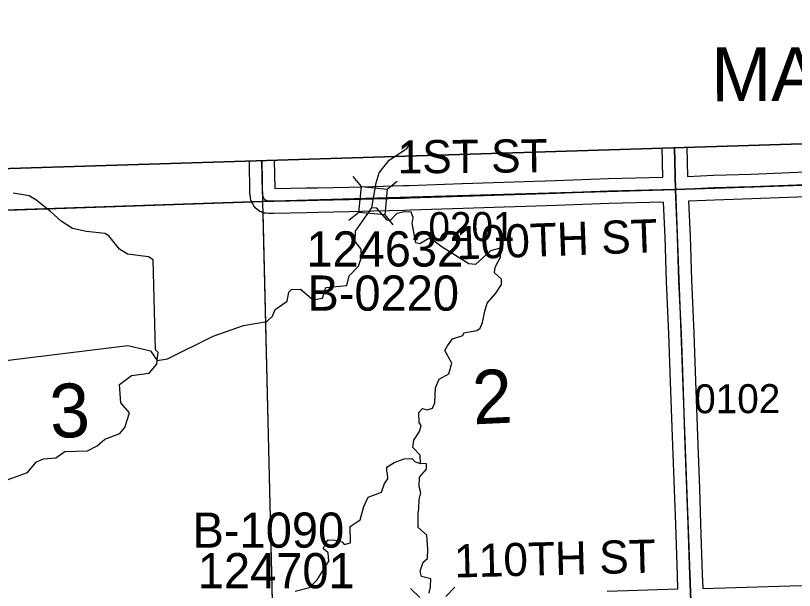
# Model space of a CAD drawing. Extents: x 128.7 to 185.5, y -21.4 to 12.6.
# Drawn here: x 143.177 to 145.06, y 3.674 to 5.063 of the extents above; entities that cross this region are included whole.
import ezdxf

# ---------------------------------------------------------------- set-up
doc = ezdxf.new("R2010")
doc.units = 0
for name, color, linetype in [('tdCoClipBndry', 7, 'Continuous'), ('tdCoCoAdjSecRdTxt', 7, 'Continuous'), ('tdCoCoBndry', 7, 'Continuous'), ('tdCoCoBndryPart', 7, 'Continuous'), ('tdCoCorpTxt', 7, 'Continuous'), ('tdCoHydroRiver', 7, 'Continuous'), ('tdCoSecRdNmbr', 7, 'Continuous'), ('tdCoSecRdTxt', 7, 'Continuous'), ('tdCoSecRteBand', 7, 'Continuous'), ('tdCoSecRteCL', 7, 'Continuous'), ('tdCoSectLine', 7, 'Continuous'), ('tdCoSectLinePart', 7, 'Continuous'), ('tdCoSectNmbr', 7, 'Continuous'), ('tdCoStrucSec', 7, 'Continuous'), ('tdCoStrucSecCoName', 7, 'Continuous'), ('tdCoStrucSecFHWANum', 7, 'Continuous'), ('tdCoSurfGravel', 7, 'Continuous'), ('tdCoTwpBndryShd', 7, 'Continuous')]:
    doc.layers.add(name, color=color, linetype=linetype)

msp = doc.modelspace()

# ---------------------------------------------------------------- linework, layer by layer
at = {"layer": 'tdCoClipBndry'}
msp.add_lwpolyline([(134.0612, -7.7025), (133.8962, -2.6807), (133.6887, 4.3446), (133.6938, 4.3792), (133.7053, 4.4028), (133.7226, 4.4226), (133.7445, 4.4372), (133.7868, 4.4475), (134.771, 4.4649), (135.7559, 4.4935), (136.7866, 4.5129), (139.7725, 4.5879), (146.7594, 4.806), (147.7608, 4.8492), (149.7557, 4.9088), (150.75, 4.946), (153.7332, 5.0633)], dxfattribs=at)
at = {"layer": 'tdCoCoBndry'}
for p, q in [((144.7722, 4.6433), (145.7757, 4.6779)), ((145.7757, 4.6779), (144.7722, 4.6433)), ((143.7746, 4.6139), (144.7722, 4.6433)), ((144.7722, 4.6433), (143.7746, 4.6139)), ((142.7681, 4.58), (143.7746, 4.6139)), ((143.7746, 4.6139), (142.7681, 4.58))]:
    msp.add_line(p, q, dxfattribs=at)
for points in [[(153.7332, 5.0633), (150.75, 4.946), (149.7557, 4.9088), (147.7608, 4.8492), (146.7594, 4.806), (139.7725, 4.5879), (136.7866, 4.5129)], [(136.7888, 4.4129), (137.7724, 4.4375), (137.7858, 4.438), (138.7769, 4.4617), (139.7753, 4.488), (140.7687, 4.5163), (141.7663, 4.5476), (142.7677, 4.58), (143.7742, 4.6139), (144.7719, 4.6433), (145.7753, 4.6779), (146.7631, 4.7061), (147.7638, 4.7493), (148.7588, 4.7767), (149.759, 4.8089), (150.7538, 4.8461), (150.7626, 4.8466), (151.7683, 4.8866), (152.7453, 4.9271), (153.73, 4.9634)], [(136.7891, 4.4129), (137.7728, 4.4375), (137.7862, 4.438), (138.7773, 4.4617), (139.7757, 4.488), (140.769, 4.5163), (141.7667, 4.5476), (142.7681, 4.58), (143.7746, 4.6139), (144.7722, 4.6433), (145.7757, 4.6779), (146.7635, 4.7061), (147.7642, 4.7493), (148.7592, 4.7767), (149.7594, 4.8089), (150.7542, 4.8461), (150.7629, 4.8466), (151.7687, 4.8866), (152.7457, 4.9271), (153.7304, 4.9634)], [(136.7891, 4.4129), (137.7728, 4.4375), (137.7862, 4.438), (138.7773, 4.4617), (139.7757, 4.488), (140.769, 4.5163), (141.7667, 4.5476), (142.7681, 4.58), (143.7746, 4.6139), (144.7722, 4.6433), (145.7757, 4.6779), (146.7635, 4.7061), (147.7642, 4.7493), (148.7592, 4.7767), (149.7594, 4.8089), (150.7542, 4.8461), (150.7629, 4.8466), (151.7687, 4.8866), (152.7457, 4.9271), (153.7304, 4.9634)]]:
    msp.add_lwpolyline(points, dxfattribs=at)
at = {"layer": 'tdCoCoBndryPart'}
msp.add_lwpolyline([(142.2951, 4.5647), (142.7677, 4.58), (143.7477, 4.613)], dxfattribs=at)
at = {"layer": 'tdCoHydroRiver'}
for points in [[(143.1297, 3.9317), (143.2061, 3.9595), (143.2274, 3.9854), (143.2445, 3.9923), (143.2744, 3.9949), (143.296, 4.0098), (143.3512, 4.0116), (143.3745, 4.0234), (143.3929, 4.0398), (143.4288, 4.0536), (143.4409, 4.0682), (143.4524, 4.1033), (143.4311, 4.1279), (143.4281, 4.172), (143.4574, 4.1934), (143.4998, 4.1996), (143.5181, 4.2207), (143.5193, 4.2302), (143.5445, 4.2342), (143.6548, 4.2883), (143.7281, 4.3143), (143.7847, 4.3241), (143.7984, 4.3372), (143.8042, 4.3531), (143.8336, 4.373), (143.8376, 4.3953), (143.8437, 4.4018), (143.8658, 4.4025), (143.8966, 4.3767), (143.9186, 4.3805), (143.9272, 4.4061), (143.9776, 4.4109), (143.9831, 4.4347), (144.0061, 4.4576), (144.0132, 4.4799), (144.0126, 4.4989), (143.9978, 4.5173), (143.9986, 4.5426), (144.0378, 4.5991), (144.0484, 4.6595), (144.0555, 4.6834), (144.0798, 4.7142), (144.1231, 4.7424), (144.133, 4.7589)], [(142.9691, 4.2075), (143.4487, 4.2658), (143.5028, 4.2533), (143.5193, 4.2302), (143.5219, 4.2492), (143.5154, 4.2553), (143.5099, 4.473), (143.4986, 4.4805), (143.4478, 4.4868), (143.4285, 4.4988), (143.4022, 4.531), (143.3925, 4.537), (143.3482, 4.5419), (143.3148, 4.5487), (143.2874, 4.5668), (143.2614, 4.5896), (143.2257, 4.6184), (143.2096, 4.6274), (143.1715, 4.634)], [(143.8532, 3.6728), (143.8877, 3.6818), (143.906, 3.6997), (143.9345, 3.7449), (143.9323, 3.7653), (143.9209, 3.776), (143.9268, 3.7888), (143.9329, 3.7969), (143.9487, 3.7958), (143.9662, 3.7917), (143.9711, 3.7855), (143.9868, 3.7892), (143.9855, 3.8286), (144.0102, 3.8452), (144.0187, 3.8771), (144.029, 3.8995), (144.0617, 3.9116), (144.0689, 3.9324), (144.0765, 3.9437), (144.076, 3.9579), (144.0743, 3.961), (144.074, 3.972), (144.0925, 3.9837), (144.1159, 3.9923), (144.1349, 3.9929), (144.143, 3.9853), (144.1558, 3.981), (144.1551, 4.0015), (144.1371, 4.0198), (144.1397, 4.0373), (144.1533, 4.0583), (144.1575, 4.0726), (144.1525, 4.0803), (144.1518, 4.104), (144.1609, 4.1138), (144.1721, 4.111), (144.1846, 4.1145), (144.1905, 4.1274), (144.1924, 4.1637), (144.2012, 4.1845), (144.2245, 4.1979), (144.2315, 4.2234), (144.2147, 4.2544), (144.2207, 4.2657), (144.2328, 4.2819), (144.2578, 4.2906), (144.2607, 4.297), (144.2921, 4.3027), (144.2998, 4.3077), (144.3057, 4.3221), (144.3111, 4.3491), (144.3168, 4.3683), (144.3381, 4.3926), (144.3516, 4.4136), (144.3512, 4.4262), (144.3349, 4.4415), (144.3361, 4.4557), (144.3495, 4.4798), (144.3489, 4.4972), (144.3457, 4.5002), (144.3253, 4.4948), (144.2885, 4.4621), (144.2727, 4.4631), (144.2082, 4.5037), (144.1823, 4.5233), (144.1759, 4.5247), (144.1543, 4.5114), (144.1447, 4.5142), (144.1353, 4.5613), (144.138, 4.5756), (144.1328, 4.588), (144.117, 4.5891), (144.0982, 4.5853), (144.0814, 4.5674), (144.0751, 4.5688), (144.0504, 4.598), (144.0378, 4.5991)], [(144.177, 3.6675), (144.1797, 3.6834), (144.1806, 3.7024), (144.1583, 3.708), (144.1548, 3.7205), (144.1619, 3.7428), (144.1727, 3.7511), (144.1736, 3.7732), (144.1709, 3.8078), (144.1498, 3.8261), (144.1502, 3.8608), (144.1514, 3.8719), (144.1523, 3.894), (144.1565, 3.91), (144.1528, 3.9256), (144.1537, 3.9478), (144.1704, 3.9673), (144.17, 3.9799), (144.1558, 3.981)]]:
    msp.add_lwpolyline(points, dxfattribs=at)
at = {"layer": 'tdCoSecRteBand'}
msp.add_line((143.8022, 4.7137), (143.8033, 4.6452), dxfattribs=at)
for points in [[(144.7997, 4.7448), (144.8015, 4.6747), (144.8639, 4.6776), (144.8641, 4.6776), (144.8643, 4.6776), (144.9547, 4.6803), (145.0862, 4.6855), (145.0863, 4.6855), (145.0864, 4.6855), (145.2677, 4.6914), (145.2678, 4.6914), (145.2678, 4.6914), (145.4308, 4.6961), (145.573, 4.7005), (145.5732, 4.7005), (145.5733, 4.7005), (145.643, 4.702), (145.652, 4.7023), (145.652, 4.7023), (145.652, 4.7023), (145.6712, 4.7029), (145.7438, 4.7064), (145.7418, 4.7742)], [(143.8033, 4.6452), (143.8792, 4.6467), (143.8792, 4.6467), (143.8792, 4.6467), (143.907, 4.6472), (143.9826, 4.6489), (144.0409, 4.6504), (144.1149, 4.6524), (144.1278, 4.6531), (144.1281, 4.6531), (144.1284, 4.6531), (144.2568, 4.6573), (144.2568, 4.6573), (144.2569, 4.6573), (144.4824, 4.6645), (144.61, 4.6694), (144.6103, 4.6694), (144.6105, 4.6694), (144.7415, 4.6726), (144.7397, 4.743)], [(144.6072, 3.6725), (144.7781, 3.6785), (144.7766, 3.7101), (144.7766, 3.7103), (144.7766, 3.7105), (144.7726, 3.8333), (144.7726, 3.8333), (144.7726, 3.8333), (144.7699, 3.9183), (144.7657, 4.0242), (144.7657, 4.0243), (144.7657, 4.0244), (144.7603, 4.178), (144.7603, 4.178), (144.7603, 4.178), (144.7564, 4.294), (144.7505, 4.4211), (144.7504, 4.4213), (144.7504, 4.4215), (144.7472, 4.5281), (144.7435, 4.6126), (144.743, 4.6126), (144.743, 4.6126), (144.6121, 4.6094), (144.4846, 4.6045), (144.4845, 4.6045), (144.4844, 4.6045), (144.2588, 4.5973), (144.1306, 4.5931), (144.1177, 4.5925), (144.1173, 4.5925), (144.1169, 4.5925), (144.0426, 4.5904), (144.0425, 4.5904), (144.0425, 4.5904), (143.9841, 4.5889), (143.9841, 4.5889), (143.984, 4.5889), (143.9083, 4.5872), (143.9082, 4.5872), (143.9082, 4.5872), (143.8803, 4.5867), (143.8007, 4.5852), (143.7918, 4.585), (143.7904, 4.585), (143.7889, 4.5851), (143.7827, 4.5856), (143.7825, 4.5856), (143.7777, 4.5859), (143.7733, 4.5878), (143.7703, 4.589), (143.7672, 4.5903), (143.7644, 4.5923), (143.761, 4.5948), (143.7558, 4.5985), (143.7526, 4.604), (143.7519, 4.6052), (143.7501, 4.6082), (143.7485, 4.6109), (143.7475, 4.6139), (143.746, 4.6183), (143.7451, 4.621), (143.7447, 4.6237), (143.7438, 4.6309), (143.7435, 4.6327), (143.7435, 4.6345), (143.7422, 4.7118)], [(145.0885, 4.6255), (144.9569, 4.6203), (144.9568, 4.6203), (144.9566, 4.6203), (144.8664, 4.6176), (144.8035, 4.6147), (144.8072, 4.5305), (144.8072, 4.5303), (144.8072, 4.5301), (144.8104, 4.4236), (144.8163, 4.2966), (144.8163, 4.2964), (144.8163, 4.2962), (144.8203, 4.1801), (144.8257, 4.0265), (144.8299, 3.9206), (144.8299, 3.9204), (144.8299, 3.9203), (144.8326, 3.8352), (144.8365, 3.7127), (144.838, 3.68), (144.8381, 3.6788)], [(144.8381, 3.6788), (145.049, 3.6851), (145.0492, 3.6851), (145.0494, 3.6851), (145.1937, 3.6875)]]:
    msp.add_lwpolyline(points, dxfattribs=at)
at = {"layer": 'tdCoSecRteCL'}
msp.add_line((144.7722, 4.6433), (144.7697, 4.7439), dxfattribs=at)
for points in [[(144.7722, 4.6433), (144.6112, 4.6394), (144.4835, 4.6345), (144.2578, 4.6273), (144.1293, 4.6231), (144.1161, 4.6224), (144.0417, 4.6204), (143.9833, 4.6189), (143.9076, 4.6172), (143.8798, 4.6167), (143.8002, 4.6152), (143.7912, 4.615), (143.785, 4.6155), (143.7848, 4.6155), (143.7819, 4.6167), (143.7784, 4.6192), (143.7777, 4.6204), (143.7759, 4.6234), (143.7745, 4.6278), (143.7735, 4.635), (143.7722, 4.7128)], [(144.7722, 4.6433), (144.8652, 4.6476), (144.9557, 4.6503), (145.0874, 4.6555), (145.2687, 4.6614), (145.4317, 4.6661), (145.574, 4.6705), (145.6438, 4.672), (145.6529, 4.6723), (145.6723, 4.6729), (145.7631, 4.6774), (145.77, 4.6778), (145.7757, 4.6779)], [(144.8095, 3.6487), (144.8066, 3.7115), (144.8026, 3.8343), (144.7999, 3.9194), (144.7957, 4.0254), (144.7903, 4.179), (144.7863, 4.2952), (144.7804, 4.4224), (144.7772, 4.5292), (144.7722, 4.6433)]]:
    msp.add_lwpolyline(points, dxfattribs=at)
at = {"layer": 'tdCoSectLine'}
for points in [[(144.7694, 4.7439), (144.7719, 4.6433)], [(143.7723, 4.7128), (143.7742, 4.6139)], [(144.7719, 4.6433), (145.7753, 4.6779)], [(143.7742, 4.6139), (144.7719, 4.6433)], [(144.7719, 4.6433), (144.8091, 3.6487)], [(142.7677, 4.58), (143.7742, 4.6139)], [(143.7742, 4.6139), (143.7981, 3.6168)]]:
    msp.add_lwpolyline(points, dxfattribs=at)
at = {"layer": 'tdCoSectLinePart'}
for points in [[(142.7677, 4.58), (143.7477, 4.613)], [(143.7748, 4.5871), (143.7974, 3.6467)]]:
    msp.add_lwpolyline(points, dxfattribs=at)
at = {"layer": 'tdCoStrucSec'}
for p, q in [((144.0132, 4.65), (143.9934, 4.6742)), ((144.0755, 4.6438), (144.0997, 4.6636)), ((144.007, 4.5877), (143.9828, 4.5679)), ((144.0693, 4.5815), (144.0891, 4.5573)), ((144.1545, 3.6576), (144.1317, 3.6791)), ((144.2171, 3.6595), (144.2386, 3.6822))]:
    msp.add_line(p, q, dxfattribs=at)
msp.add_lwpolyline([(144.0132, 4.65), (144.0755, 4.6438), (144.0693, 4.5815), (144.007, 4.5877)], close=True, dxfattribs=at)
at = {"layer": 'tdCoSurfGravel'}
for p, q in [((144.7722, 4.6433), (144.7697, 4.7439)), ((143.785, 4.6155), (143.7912, 4.615))]:
    msp.add_line(p, q, dxfattribs=at)
for points in [[(143.785, 4.6155), (143.7848, 4.6155), (143.7819, 4.6167), (143.7784, 4.6192), (143.7777, 4.6204), (143.7759, 4.6234), (143.7745, 4.6278), (143.7735, 4.635), (143.7722, 4.7128)], [(143.7912, 4.615), (143.8002, 4.6152), (143.8798, 4.6167), (143.9076, 4.6172), (143.9833, 4.6189), (144.0417, 4.6204), (144.1161, 4.6224), (144.1293, 4.6231), (144.2578, 4.6273), (144.4835, 4.6345), (144.6112, 4.6394), (144.7722, 4.6433), (144.8652, 4.6476), (144.9557, 4.6503), (145.0874, 4.6555), (145.2687, 4.6614), (145.4317, 4.6661), (145.574, 4.6705), (145.6438, 4.672), (145.6529, 4.6723), (145.6723, 4.6729), (145.7631, 4.6774), (145.77, 4.6778), (145.7757, 4.6779)], [(144.8095, 3.6487), (144.8066, 3.7115), (144.8026, 3.8343), (144.7999, 3.9194), (144.7957, 4.0254), (144.7903, 4.179), (144.7863, 4.2952), (144.7804, 4.4224), (144.7772, 4.5292), (144.7722, 4.6433)]]:
    msp.add_lwpolyline(points, dxfattribs=at)
at = {"layer": 'tdCoTwpBndryShd'}
msp.add_lwpolyline([(153.73, 4.9634), (152.7453, 4.9271), (151.7683, 4.8866), (150.7626, 4.8466), (150.7538, 4.8461), (149.759, 4.8089), (148.7588, 4.7767), (147.7638, 4.7493), (146.7631, 4.7061), (145.7753, 4.6779), (144.7719, 4.6433), (143.7742, 4.6139), (142.7677, 4.58), (141.7663, 4.5476), (140.7687, 4.5163), (139.7753, 4.488), (138.7769, 4.4617), (137.7858, 4.438), (137.7724, 4.4375), (136.7888, 4.4129)], dxfattribs=at)

# ---------------------------------------------------------------- texts
at = {"layer": 'tdCoCoAdjSecRdTxt'}
msp.add_text('1ST ST', height=0.08, rotation=0.5067, dxfattribs=at).set_placement((144.1008, 4.6817))
at = {"layer": 'tdCoCorpTxt'}
msp.add_text('MAQUOKETA', height=0.13, rotation=0.1, dxfattribs=at).set_placement((144.8586, 4.8564))
at = {"layer": 'tdCoSecRdNmbr'}
for s, rotation, p in [('0201', 0.1098, (144.175, 4.5184)), ('0102', 0.1102, (144.8173, 4.1024))]:
    msp.add_text(s, height=0.07, rotation=rotation, dxfattribs=at).set_placement(p)
at = {"layer": 'tdCoSecRdTxt'}
for s, rotation, p in [('100TH ST', 2.1469, (144.2433, 4.4737)), ('110TH ST', 1.44, (144.238, 3.7054))]:
    msp.add_text(s, height=0.08, rotation=rotation, dxfattribs=at).set_placement(p)
at = {"layer": 'tdCoSectNmbr'}
for s, rotation, p in [('2', 2.6622, (144.2838, 4.0755)), ('3', 2.6614, (143.2623, 4.042))]:
    msp.add_text(s, height=0.13, rotation=rotation, dxfattribs=at).set_placement(p)
at = {"layer": 'tdCoStrucSecCoName'}
for s, p in [('B-0220', (143.8824, 4.3503)), ('B-1090', (143.6048, 3.7776))]:
    msp.add_text(s, height=0.085, dxfattribs=at).set_placement(p)
at = {"layer": 'tdCoStrucSecFHWANum'}
for s, p in [('124632', (143.8798, 4.457)), ('124701', (143.6174, 3.6796))]:
    msp.add_text(s, height=0.085, dxfattribs=at).set_placement(p)

doc.saveas('drawing.dxf')
